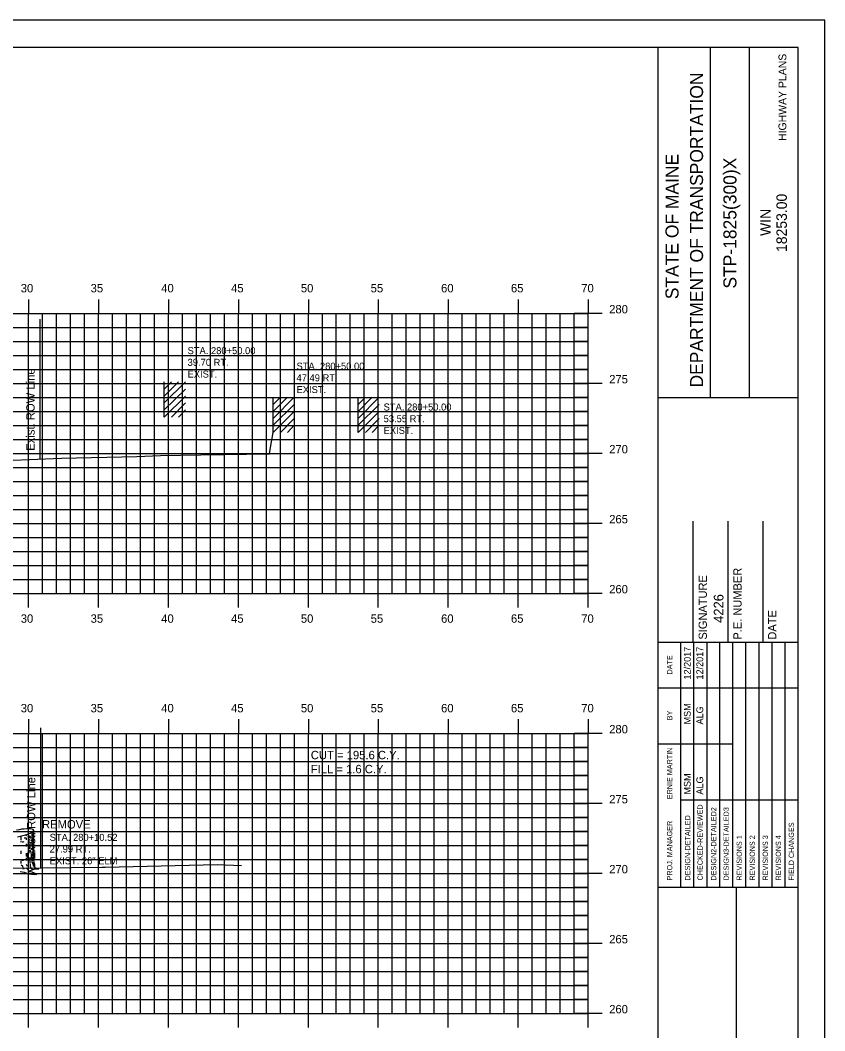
# Model space of a CAD drawing. Extents: x 855121 to 855291, y 366268 to 366378.
# Drawn here: x 855233.9 to 855291.3, y 366306 to 366378.2 of the extents above; entities that cross this region are included whole.
import ezdxf

# ---------------------------------------------------------------- set-up
doc = ezdxf.new("R2010")
doc.units = 0
for name, color, linetype in [('ANNOTATION', 7, 'Continuous'), ('BORDER', 7, 'Continuous'), ('D_Text_Monospaced', 7, 'Continuous'), ('E_ROW_Line', 7, 'Continuous'), ('H_V ANNOTATION', 7, 'Continuous'), ('HIGHWAY_TITLE', 7, 'Continuous'), ('MAJOR', 7, 'Continuous'), ('MINOR', 7, 'Continuous'), ('PLOT BOUNDARY', 7, 'Continuous'), ('S_Buildings', 7, 'Continuous'), ('S_Buildings_Attachments', 7, 'Continuous'), ('S_Roadway_Centerline', 7, 'Continuous'), ('S_Trees_Decid_Pay', 7, 'Continuous')]:
    doc.layers.add(name, color=color, linetype=linetype)

msp = doc.modelspace()

# ---------------------------------------------------------------- linework, layer by layer
at = {"layer": 'BORDER'}
for p, q in [((855289.442, 366376.236), (855129.442, 366376.236)), ((855279.442, 366271.236), (855279.442, 366376.239)), ((855283.171, 366351.234), (855283.171, 366376.234)), ((855285.966, 366351.234), (855285.966, 366376.234)), ((855289.442, 366271.236), (855289.442, 366376.236)), ((855279.443, 366351.231), (855289.442, 366351.231)), ((855281.942, 366333.739), (855281.942, 366342.387)), ((855284.442, 366333.739), (855284.442, 366342.387)), ((855286.942, 366333.739), (855286.942, 366342.387)), ((855279.442, 366333.739), (855289.442, 366333.739)), ((855279.442, 366316.239), (855289.442, 366316.239)), ((855285.033, 366281.239), (855285.033, 366316.239))]:
    msp.add_line(p, q, dxfattribs=at)
for points in [[(855281.057, 366330.489), (855281.057, 366333.739)], [(855281.99, 366316.242), (855281.99, 366333.739)], [(855282.921, 366333.739), (855282.921, 366316.242)], [(855283.853, 366316.242), (855283.853, 366333.739)], [(855284.785, 366316.242), (855284.785, 366333.739)], [(855285.716, 366316.242), (855285.716, 366333.739)], [(855286.648, 366316.242), (855286.648, 366333.739)], [(855287.58, 366316.242), (855287.58, 366333.739)], [(855288.511, 366316.242), (855288.511, 366333.739)], [(855281.058, 366316.242), (855281.058, 366333.033)], [(855279.442, 366330.489), (855289.442, 366330.489)], [(855279.442, 366326.489), (855281.058, 366326.489)], [(855281.057, 366326.489), (855284.784, 366326.489)], [(855281.057, 366322.489), (855289.442, 366322.489)]]:
    msp.add_lwpolyline(points, dxfattribs=at)
at = {"layer": 'E_ROW_Line'}
for p, q in [((855235.284, 366346.822), (855235.284, 366356.822)), ((855235.331, 366317.628), (855235.331, 366327.628))]:
    msp.add_line(p, q, dxfattribs=at)
at = {"layer": 'MAJOR'}
for p, q in [((855234.442, 366358.238), (855234.442, 366357.236)), ((855239.442, 366358.238), (855239.442, 366357.236)), ((855244.442, 366358.238), (855244.442, 366357.236)), ((855249.442, 366358.238), (855249.442, 366357.236)), ((855254.442, 366358.238), (855254.442, 366357.236)), ((855259.442, 366358.238), (855259.442, 366357.236)), ((855264.442, 366358.238), (855264.442, 366357.236)), ((855269.442, 366358.238), (855269.442, 366357.236)), ((855274.442, 366358.238), (855274.442, 366357.236)), ((855134.442, 366357.236), (855274.442, 366357.236)), ((855134.442, 366357.236), (855274.442, 366357.236)), ((855234.442, 366337.236), (855234.442, 366357.236)), ((855239.442, 366337.236), (855239.442, 366357.236)), ((855244.442, 366337.236), (855244.442, 366357.236)), ((855249.442, 366337.236), (855249.442, 366357.236)), ((855254.442, 366337.236), (855254.442, 366357.236)), ((855259.442, 366337.236), (855259.442, 366357.236)), ((855264.442, 366337.236), (855264.442, 366357.236)), ((855269.442, 366337.236), (855269.442, 366357.236)), ((855275.444, 366357.236), (855273.44, 366357.236)), ((855274.442, 366337.236), (855274.442, 366357.236)), ((855274.442, 366337.236), (855274.442, 366357.236)), ((855134.442, 366352.236), (855274.442, 366352.236)), ((855275.444, 366352.236), (855273.44, 366352.236)), ((855134.442, 366347.236), (855274.442, 366347.236)), ((855275.444, 366347.236), (855273.44, 366347.236)), ((855134.442, 366342.236), (855274.442, 366342.236)), ((855275.444, 366342.236), (855273.44, 366342.236)), ((855134.442, 366337.236), (855274.442, 366337.236)), ((855134.442, 366337.236), (855274.442, 366337.236)), ((855234.442, 366336.234), (855234.442, 366337.236)), ((855239.442, 366336.234), (855239.442, 366337.236)), ((855244.442, 366336.234), (855244.442, 366337.236)), ((855249.442, 366336.234), (855249.442, 366337.236)), ((855254.442, 366336.234), (855254.442, 366337.236)), ((855259.442, 366336.234), (855259.442, 366337.236)), ((855264.442, 366336.234), (855264.442, 366337.236)), ((855269.442, 366336.234), (855269.442, 366337.236)), ((855275.444, 366337.236), (855273.44, 366337.236)), ((855274.442, 366336.234), (855274.442, 366337.236)), ((855234.442, 366328.238), (855234.442, 366327.236)), ((855239.442, 366328.238), (855239.442, 366327.236)), ((855244.442, 366328.238), (855244.442, 366327.236)), ((855249.442, 366328.238), (855249.442, 366327.236)), ((855254.442, 366328.238), (855254.442, 366327.236)), ((855259.442, 366328.238), (855259.442, 366327.236)), ((855264.442, 366328.238), (855264.442, 366327.236)), ((855269.442, 366328.238), (855269.442, 366327.236)), ((855274.442, 366328.238), (855274.442, 366327.236)), ((855134.442, 366327.236), (855274.442, 366327.236)), ((855134.442, 366327.236), (855274.442, 366327.236)), ((855234.442, 366307.236), (855234.442, 366327.236)), ((855239.442, 366307.236), (855239.442, 366327.236)), ((855244.442, 366307.236), (855244.442, 366327.236)), ((855249.442, 366307.236), (855249.442, 366327.236)), ((855254.442, 366307.236), (855254.442, 366327.236)), ((855259.442, 366307.236), (855259.442, 366327.236)), ((855264.442, 366307.236), (855264.442, 366327.236)), ((855269.442, 366307.236), (855269.442, 366327.236)), ((855275.444, 366327.236), (855273.44, 366327.236)), ((855274.442, 366307.236), (855274.442, 366327.236)), ((855274.442, 366307.236), (855274.442, 366327.236)), ((855134.442, 366322.236), (855274.442, 366322.236)), ((855275.444, 366322.236), (855273.44, 366322.236)), ((855134.442, 366317.236), (855274.442, 366317.236)), ((855275.444, 366317.236), (855273.44, 366317.236)), ((855134.442, 366312.236), (855274.442, 366312.236)), ((855275.444, 366312.236), (855273.44, 366312.236)), ((855134.442, 366307.236), (855274.442, 366307.236)), ((855134.442, 366307.236), (855274.442, 366307.236)), ((855234.442, 366306.234), (855234.442, 366307.236)), ((855239.442, 366306.234), (855239.442, 366307.236)), ((855244.442, 366306.234), (855244.442, 366307.236)), ((855249.442, 366306.234), (855249.442, 366307.236)), ((855254.442, 366306.234), (855254.442, 366307.236)), ((855259.442, 366306.234), (855259.442, 366307.236)), ((855264.442, 366306.234), (855264.442, 366307.236)), ((855269.442, 366306.234), (855269.442, 366307.236)), ((855275.444, 366307.236), (855273.44, 366307.236)), ((855274.442, 366306.234), (855274.442, 366307.236))]:
    msp.add_line(p, q, dxfattribs=at)
at = {"layer": 'MINOR'}
for p, q in [((855235.442, 366337.236), (855235.442, 366357.236)), ((855236.442, 366337.236), (855236.442, 366357.236)), ((855237.442, 366337.236), (855237.442, 366357.236)), ((855238.442, 366337.236), (855238.442, 366357.236)), ((855240.442, 366337.236), (855240.442, 366357.236)), ((855241.442, 366337.236), (855241.442, 366357.236)), ((855242.442, 366337.236), (855242.442, 366357.236)), ((855243.442, 366337.236), (855243.442, 366357.236)), ((855245.442, 366337.236), (855245.442, 366357.236)), ((855246.442, 366337.236), (855246.442, 366357.236)), ((855247.442, 366337.236), (855247.442, 366357.236)), ((855248.442, 366337.236), (855248.442, 366357.236)), ((855250.442, 366337.236), (855250.442, 366357.236)), ((855251.442, 366337.236), (855251.442, 366357.236)), ((855252.442, 366337.236), (855252.442, 366357.236)), ((855253.442, 366337.236), (855253.442, 366357.236)), ((855255.442, 366337.236), (855255.442, 366357.236)), ((855256.442, 366337.236), (855256.442, 366357.236)), ((855257.442, 366337.236), (855257.442, 366357.236)), ((855258.442, 366337.236), (855258.442, 366357.236)), ((855260.442, 366337.236), (855260.442, 366357.236)), ((855261.442, 366337.236), (855261.442, 366357.236)), ((855262.442, 366337.236), (855262.442, 366357.236)), ((855263.442, 366337.236), (855263.442, 366357.236)), ((855265.442, 366337.236), (855265.442, 366357.236)), ((855266.442, 366337.236), (855266.442, 366357.236)), ((855267.442, 366337.236), (855267.442, 366357.236)), ((855268.442, 366337.236), (855268.442, 366357.236)), ((855270.442, 366337.236), (855270.442, 366357.236)), ((855271.442, 366337.236), (855271.442, 366357.236)), ((855272.442, 366337.236), (855272.442, 366357.236)), ((855273.442, 366337.236), (855273.442, 366357.236)), ((855134.442, 366356.236), (855274.442, 366356.236)), ((855274.442, 366356.236), (855273.44, 366356.236)), ((855134.442, 366355.236), (855274.442, 366355.236)), ((855274.442, 366355.236), (855273.44, 366355.236)), ((855134.442, 366354.236), (855274.442, 366354.236)), ((855274.442, 366354.236), (855273.44, 366354.236)), ((855134.442, 366353.236), (855274.442, 366353.236)), ((855274.442, 366353.236), (855273.44, 366353.236)), ((855134.442, 366351.236), (855274.442, 366351.236)), ((855274.442, 366351.236), (855273.44, 366351.236)), ((855134.442, 366350.236), (855274.442, 366350.236)), ((855274.442, 366350.236), (855273.44, 366350.236)), ((855134.442, 366349.236), (855274.442, 366349.236)), ((855274.442, 366349.236), (855273.44, 366349.236)), ((855134.442, 366348.236), (855274.442, 366348.236)), ((855274.442, 366348.236), (855273.44, 366348.236)), ((855134.442, 366346.236), (855274.442, 366346.236)), ((855274.442, 366346.236), (855273.44, 366346.236)), ((855134.442, 366345.236), (855274.442, 366345.236)), ((855274.442, 366345.236), (855273.44, 366345.236)), ((855134.442, 366344.236), (855274.442, 366344.236)), ((855274.442, 366344.236), (855273.44, 366344.236)), ((855134.442, 366343.236), (855274.442, 366343.236)), ((855274.442, 366343.236), (855273.44, 366343.236)), ((855134.442, 366341.236), (855274.442, 366341.236)), ((855274.442, 366341.236), (855273.44, 366341.236)), ((855134.442, 366340.236), (855274.442, 366340.236)), ((855274.442, 366340.236), (855273.44, 366340.236)), ((855134.442, 366339.236), (855274.442, 366339.236)), ((855274.442, 366339.236), (855273.44, 366339.236)), ((855134.442, 366338.236), (855274.442, 366338.236)), ((855274.442, 366338.236), (855273.44, 366338.236)), ((855235.442, 366307.236), (855235.442, 366327.236)), ((855236.442, 366307.236), (855236.442, 366327.236)), ((855237.442, 366307.236), (855237.442, 366327.236)), ((855238.442, 366307.236), (855238.442, 366327.236)), ((855240.442, 366307.236), (855240.442, 366327.236)), ((855241.442, 366307.236), (855241.442, 366327.236)), ((855242.442, 366307.236), (855242.442, 366327.236)), ((855243.442, 366307.236), (855243.442, 366327.236)), ((855245.442, 366307.236), (855245.442, 366327.236)), ((855246.442, 366307.236), (855246.442, 366327.236)), ((855247.442, 366307.236), (855247.442, 366327.236)), ((855248.442, 366307.236), (855248.442, 366327.236)), ((855250.442, 366307.236), (855250.442, 366327.236)), ((855251.442, 366307.236), (855251.442, 366327.236)), ((855252.442, 366307.236), (855252.442, 366327.236)), ((855253.442, 366307.236), (855253.442, 366327.236)), ((855255.442, 366307.236), (855255.442, 366327.236)), ((855256.442, 366307.236), (855256.442, 366327.236)), ((855257.442, 366307.236), (855257.442, 366327.236)), ((855258.442, 366307.236), (855258.442, 366327.236)), ((855260.442, 366307.236), (855260.442, 366327.236)), ((855261.442, 366307.236), (855261.442, 366327.236)), ((855262.442, 366307.236), (855262.442, 366327.236)), ((855263.442, 366307.236), (855263.442, 366327.236)), ((855265.442, 366307.236), (855265.442, 366327.236)), ((855266.442, 366307.236), (855266.442, 366327.236)), ((855267.442, 366307.236), (855267.442, 366327.236)), ((855268.442, 366307.236), (855268.442, 366327.236)), ((855270.442, 366307.236), (855270.442, 366327.236)), ((855271.442, 366307.236), (855271.442, 366327.236)), ((855272.442, 366307.236), (855272.442, 366327.236)), ((855273.442, 366307.236), (855273.442, 366327.236)), ((855134.442, 366326.236), (855274.442, 366326.236)), ((855274.442, 366326.236), (855273.44, 366326.236)), ((855134.442, 366325.236), (855274.442, 366325.236)), ((855274.442, 366325.236), (855273.44, 366325.236)), ((855134.442, 366324.236), (855274.442, 366324.236)), ((855274.442, 366324.236), (855273.44, 366324.236)), ((855134.442, 366323.236), (855274.442, 366323.236)), ((855274.442, 366323.236), (855273.44, 366323.236)), ((855134.442, 366321.236), (855274.442, 366321.236)), ((855274.442, 366321.236), (855273.44, 366321.236)), ((855134.442, 366320.236), (855274.442, 366320.236)), ((855274.442, 366320.236), (855273.44, 366320.236)), ((855134.442, 366319.236), (855274.442, 366319.236)), ((855274.442, 366319.236), (855273.44, 366319.236)), ((855134.442, 366318.236), (855274.442, 366318.236)), ((855274.442, 366318.236), (855273.44, 366318.236)), ((855134.442, 366316.236), (855274.442, 366316.236)), ((855274.442, 366316.236), (855273.44, 366316.236)), ((855134.442, 366315.236), (855274.442, 366315.236)), ((855274.442, 366315.236), (855273.44, 366315.236)), ((855134.442, 366314.236), (855274.442, 366314.236)), ((855274.442, 366314.236), (855273.44, 366314.236)), ((855134.442, 366313.236), (855274.442, 366313.236)), ((855274.442, 366313.236), (855273.44, 366313.236)), ((855134.442, 366311.236), (855274.442, 366311.236)), ((855274.442, 366311.236), (855273.44, 366311.236)), ((855134.442, 366310.236), (855274.442, 366310.236)), ((855274.442, 366310.236), (855273.44, 366310.236)), ((855134.442, 366309.236), (855274.442, 366309.236)), ((855274.442, 366309.236), (855273.44, 366309.236)), ((855134.442, 366308.236), (855274.442, 366308.236)), ((855274.442, 366308.236), (855273.44, 366308.236))]:
    msp.add_line(p, q, dxfattribs=at)
at = {"layer": 'PLOT BOUNDARY'}
msp.add_lwpolyline([(855121.349, 366268.177), (855291.349, 366268.177), (855291.349, 366378.177), (855121.349, 366378.177)], close=True, dxfattribs=at)
at = {"layer": 'S_Buildings'}
for p, q in [((855251.931, 366348.718), (855251.931, 366351.245)), ((855251.931, 366349.735), (855253.44, 366351.245)), ((855251.931, 366350.228), (855252.948, 366351.245)), ((855251.931, 366350.72), (855252.456, 366351.245)), ((855257.991, 366348.718), (855257.991, 366351.245)), ((855257.991, 366349.736), (855259.5, 366351.245)), ((855257.991, 366350.228), (855259.008, 366351.245)), ((855257.991, 366350.72), (855258.516, 366351.245)), ((855251.931, 366349.243), (855253.44, 366350.72)), ((855257.991, 366349.243), (855259.5, 366350.72)), ((855251.931, 366348.718), (855253.44, 366350.228)), ((855252.456, 366348.718), (855253.44, 366349.735)), ((855257.991, 366348.718), (855259.5, 366350.228)), ((855258.516, 366348.718), (855259.5, 366349.736)), ((855252.948, 366348.718), (855253.44, 366349.243)), ((855259.008, 366348.718), (855259.5, 366349.243))]:
    msp.add_line(p, q, dxfattribs=at)
at = {"layer": 'S_Buildings_Attachments'}
for p, q in [((855244.146, 366349.825), (855244.146, 366352.351)), ((855244.146, 366350.842), (855245.655, 366352.351)), ((855244.146, 366351.334), (855245.163, 366352.351)), ((855244.146, 366351.826), (855244.671, 366352.351)), ((855244.146, 366350.35), (855245.655, 366351.826)), ((855244.146, 366349.825), (855245.655, 366351.334)), ((855244.671, 366349.825), (855245.655, 366350.842)), ((855245.163, 366349.825), (855245.655, 366350.35))]:
    msp.add_line(p, q, dxfattribs=at)
at = {"layer": 'S_Roadway_Centerline'}
for points in [[(855225.306, 366346.406), (855236.796, 366346.885), (855242.187, 366347.024), (855243.875, 366347.078), (855246.754, 366347.142), (855251.665, 366347.196), (855251.741, 366347.66), (855251.931, 366348.719)], [(855228.791, 366317.564), (855239.683, 366317.672), (855239.926, 366317.671), (855247.916, 366317.86), (855249.671, 366317.803)]]:
    msp.add_lwpolyline(points, dxfattribs=at)
at = {"layer": 'S_Trees_Decid_Pay'}
for p, q in [((855234.277, 366320.003), (855234.277, 366319.917)), ((855234.681, 366320.17), (855234.681, 366319.917)), ((855234.762, 366320.215), (855234.762, 366320.094)), ((855234.762, 366320.042), (855234.762, 366319.828)), ((855233.893, 366319.902), (855233.893, 366319.622)), ((855233.893, 366319.557), (855233.893, 366319.454)), ((855234.277, 366319.776), (855234.277, 366319.637)), ((855234.277, 366319.351), (855234.277, 366319.159)), ((855234.549, 366319.917), (855234.549, 366319.725)), ((855234.549, 366319.474), (855234.549, 366319.196)), ((855234.681, 366319.82), (855234.681, 366319.557)), ((855234.681, 366319.459), (855234.681, 366319.151)), ((855234.762, 366319.783), (855234.762, 366319.445)), ((855234.762, 366319.328), (855234.762, 366318.967)), ((855233.893, 366318.842), (855233.893, 366318.622)), ((855234.277, 366318.679), (855234.277, 366318.471)), ((855234.549, 366319.151), (855234.549, 366319.042)), ((855234.549, 366318.908), (855234.549, 366318.679)), ((855234.681, 366319.062), (855234.681, 366318.996)), ((855234.681, 366318.762), (855234.681, 366318.665)), ((855234.681, 366318.614), (855234.681, 366318.253)), ((855234.762, 366318.931), (855234.762, 366318.482)), ((855233.893, 366318.122), (855233.893, 366317.948)), ((855234.272, 366317.893), (855234.352, 366317.761)), ((855234.277, 366318.35), (855234.277, 366318.15)), ((855234.549, 366318.35), (855234.549, 366317.967)), ((855234.681, 366318.202), (855234.681, 366318.035)), ((855234.762, 366318.416), (855234.762, 366318.134))]:
    msp.add_line(p, q, dxfattribs=at)
for points in [[(855233.844, 366317.366), (855234.13, 366317.31), (855234.428, 366317.203), (855234.887, 366317.154), (855235.042, 366317.166), (855234.7, 366317.316), (855234.496, 366317.347), (855234.508, 366317.421), (855234.768, 366317.52), (855234.943, 366317.551), (855235.184, 366317.563), (855234.986, 366317.601), (855234.924, 366317.637), (855234.9, 366317.724), (855234.887, 366317.893), (855234.842, 366317.979), (855234.814, 366318.22), (855234.814, 366320.306)], [(855234.39, 366318.485), (855234.389, 366318.562), (855234.381, 366318.628)], [(855233.911, 366317.833), (855234.014, 366317.782), (855234.029, 366317.576), (855234.132, 366317.547)], [(855234.566, 366317.907), (855234.566, 366317.702), (855234.624, 366317.592), (855234.721, 366317.576)], [(855234.706, 366317.981), (855234.778, 366317.878), (855234.778, 366317.753)], [(855234.763, 366318.062), (855234.824, 366317.901), (855234.838, 366317.776), (855234.83, 366317.679)], [(855234.496, 366317.347), (855234.41, 366317.489), (855234.278, 366317.631)]]:
    msp.add_lwpolyline(points, dxfattribs=at)
for centre, radius, start, end in [((855234.727, 366314.304), 6.126, 93.69441, 100.77788), ((855232.524, 366325.873), 6.126, 280.77788, 287.86134), ((855234.416, 366319.121), 1.299, 78.27788, 93.69441), ((855234.005, 366321.279), 1.299, 287.86134, 303.27788), ((855234.582, 366319.924), 0.48, 69.98432, 78.27788), ((855234.455, 366320.594), 0.48, 303.27788, 311.57144), ((855234.69, 366320.22), 0.164, 55.77788, 69.98432), ((855234.664, 366320.358), 0.164, 311.57144, 325.77788), ((855234.722, 366320.267), 0.107, 45.9547, 55.77788), ((855234.715, 366320.008), 0.109, 315, 324.82628), ((855234.752, 366320.298), 0.0645, 33.27788, 45.9547), ((855234.711, 366320.326), 0.107, 325.77788, 335.60106), ((855234.75, 366319.983), 0.0657, 324.82628, 337.5), ((855234.76, 366320.303), 0.0544, 22.46002, 33.27788), ((855234.75, 366320.308), 0.0645, 335.60106, 348.27788), ((855234.767, 366320.306), 0.0467, 10.77788, 22.46002), ((855234.76, 366319.979), 0.0554, 337.5, 348.31854), ((855234.767, 366320.306), 0.0467, 359.09574, 10.77788), ((855234.76, 366320.306), 0.0544, 348.27788, 359.09574), ((855233.626, 366325.395), 5.916, 273.53821, 274.89239), ((855233.627, 366325.656), 5.916, 274.95145, 276.30875), ((855233.626, 366325.132), 5.916, 276.31835, 277.15463), ((855234.201, 366320.544), 1.292, 277.15463, 278.36619), ((855234.202, 366321.068), 1.292, 285.56513, 289.09156), ((855234.201, 366320.807), 1.292, 288.08294, 292.5), ((855234.201, 366320.544), 1.292, 291.8071, 292.5), ((855234.511, 366319.798), 0.484, 292.5, 300.80756), ((855234.511, 366320.061), 0.484, 297.41617, 300.80756), ((855234.673, 366319.788), 0.166, 300.80756, 315), ((855234.673, 366319.525), 0.166, 300.80756, 301.6001), ((855234.674, 366320.049), 0.166, 301.67004, 315), ((855234.714, 366319.748), 0.109, 315, 324.82628), ((855234.749, 366319.723), 0.0657, 324.82628, 337.5), ((855234.759, 366319.719), 0.0554, 337.5, 348.31854), ((855234.201, 366320.286), 1.292, 279.25654, 285.6105), ((855234.201, 366320.029), 1.292, 285.61049, 290.10015), ((855234.511, 366319.017), 0.484, 292.5, 300.80756), ((855234.511, 366319.54), 0.484, 294.63721, 300.80756), ((855234.673, 366319.267), 0.166, 300.80756, 315), ((855234.673, 366318.744), 0.166, 300.80756, 302.06939), ((855234.673, 366319.01), 0.166, 302.06939, 315), ((855234.714, 366319.227), 0.109, 315, 324.82628), ((855234.714, 366318.969), 0.109, 315, 324.82628), ((855234.749, 366319.202), 0.0657, 324.82628, 337.5), ((855234.749, 366318.944), 0.0657, 324.82628, 337.5), ((855234.759, 366319.198), 0.0554, 337.5, 348.31854), ((855234.759, 366318.94), 0.0554, 337.5, 348.31854), ((855234.759, 366318.675), 0.0554, 337.5, 348.31854), ((855233.626, 366324.08), 5.916, 273.26366, 274.46102), ((855233.626, 366324.351), 5.916, 276.31835, 277.15463), ((855233.626, 366324.08), 5.916, 276.31835, 277.15463), ((855234.201, 366319.764), 1.292, 277.15463, 278.37952), ((855234.201, 366319.492), 1.292, 277.15463, 278.36619), ((855234.201, 366319.492), 1.292, 285.61049, 289.15336), ((855234.211, 366319.238), 1.292, 291.36963, 292.0604), ((855234.511, 366318.488), 0.484, 292.5, 296.54992), ((855234.673, 366318.472), 0.166, 302.06939, 315), ((855234.714, 366318.432), 0.109, 315, 324.82628), ((855234.749, 366318.407), 0.0657, 324.82628, 337.5), ((855234.759, 366318.403), 0.0554, 337.5, 348.31854)]:
    msp.add_arc(centre, radius, start, end, dxfattribs=at)

# ---------------------------------------------------------------- texts
at = {"layer": 'ANNOTATION'}
msp.add_text('4226', height=0.69, rotation=90, dxfattribs=at).set_placement((855284.107, 366335.13))
for s, p in [('CUT = 195.6 C.Y.', (855254.618, 366325.386)), ('FILL = 1.6 C.Y.', (855254.618, 366324.384)), ('REMOVE', (855235.41, 366320.44))]:
    msp.add_text(s, height=0.6, dxfattribs=at).set_placement(p)
at = {"layer": 'BORDER'}
for s, height, p in [('DEPARTMENT OF TRANSPORTATION', 0.93176, (855282.649, 366351.942)), ('STATE OF MAINE', 0.93176, (855280.897, 366358.248)), ('STP-1825(300)X', 0.93176, (855285.034, 366359.008)), ('18253.00', 0.7453, (855288.638, 366361.623)), ('WIN', 0.7453, (855287.479, 366362.766)), ('P.E. NUMBER', 0.59055, (855285.403, 366333.932)), ('SIGNATURE', 0.5906, (855282.923, 366333.932)), ('DATE', 0.5906, (855287.883, 366333.932)), ('12/2017', 0.4845, (855281.765, 366331.081)), ('12/2017', 0.4845, (855282.659, 366331.081)), ('DATE', 0.3714, (855280.446, 366331.445)), ('MSM', 0.4845, (855281.765, 366327.872)), ('BY', 0.3714, (855280.446, 366328.174)), ('ALG', 0.4845, (855282.659, 366327.872)), ('ERNIE MARTIN', 0.37275, (855280.446, 366322.531)), ('MSM', 0.4845, (855281.765, 366322.863)), ('ALG', 0.4845, (855282.659, 366322.863)), ('CHECKED-REVIEWED', 0.37275, (855282.623, 366316.727)), ('DESIGN2-DETAILED2', 0.37275, (855283.592, 366316.727)), ('DESIGN3-DETAILED3', 0.37275, (855284.486, 366316.727)), ('PROJ. MANAGER', 0.37275, (855280.446, 366316.727)), ('DESIGN-DETAILED', 0.37275, (855281.729, 366316.727)), ('FIELD CHANGES', 0.37275, (855289.145, 366316.727)), ('REVISIONS 1', 0.37275, (855285.418, 366316.727)), ('REVISIONS 2', 0.37275, (855286.35, 366316.727)), ('REVISIONS 3', 0.37275, (855287.281, 366316.727)), ('REVISIONS 4', 0.37275, (855288.213, 366316.727))]:
    msp.add_text(s, height=height, rotation=90, dxfattribs=at).set_placement(p)
at = {"layer": 'D_Text_Monospaced'}
for s, height, p in [('STA. 280+50.00', 0.49998, (855245.812, 366354.323)), ('39.70 RT.', 0.5, (855245.812, 366353.489)), ('EXIST. ', 0.5, (855245.812, 366352.649)), ('STA. 280+50.00', 0.49998, (855253.598, 366353.217)), ('47.49 RT.', 0.5, (855253.598, 366352.383)), ('EXIST. ', 0.5, (855253.598, 366351.543)), ('STA. 280+50.00', 0.49998, (855259.82, 366350.297)), ('53.55 RT.', 0.5, (855259.82, 366349.463)), ('EXIST. ', 0.5, (855259.82, 366348.623)), ('STA. 280+10.52', 0.49998, (855235.955, 366319.558)), ('27.99 RT.', 0.5, (855235.955, 366318.724)), ('EXIST. 26" ELM', 0.49998, (855235.955, 366317.884))]:
    msp.add_text(s, height=height, dxfattribs=at).set_placement(p)
at = {"layer": 'E_ROW_Line'}
for p in [(855234.884, 366347.422), (855234.931, 366318.228)]:
    msp.add_text('Exist. ROW Line', height=0.6, rotation=90, dxfattribs=at).set_placement(p)
at = {"layer": 'H_V ANNOTATION'}
for s, p in [('30', (855233.891, 366358.736)), ('35', (855238.883, 366358.736)), ('40', (855243.928, 366358.736)), ('45', (855248.92, 366358.736)), ('50', (855253.907, 366358.736)), ('55', (855258.899, 366358.736)), ('60', (855263.928, 366358.736)), ('65', (855268.92, 366358.736)), ('70', (855273.944, 366358.736)), ('280', (855275.942, 366357.236)), ('275', (855275.942, 366352.236)), ('270', (855275.942, 366347.236)), ('265', (855275.942, 366342.236)), ('260', (855275.942, 366337.236)), ('30', (855233.891, 366335.136)), ('35', (855238.883, 366335.136)), ('40', (855243.928, 366335.136)), ('45', (855248.92, 366335.136)), ('50', (855253.907, 366335.136)), ('55', (855258.899, 366335.136)), ('60', (855263.928, 366335.136)), ('65', (855268.92, 366335.136)), ('70', (855273.944, 366335.136)), ('30', (855233.891, 366328.736)), ('35', (855238.883, 366328.736)), ('40', (855243.928, 366328.736)), ('45', (855248.92, 366328.736)), ('50', (855253.907, 366328.736)), ('55', (855258.899, 366328.736)), ('60', (855263.928, 366328.736)), ('65', (855268.92, 366328.736)), ('70', (855273.944, 366328.736)), ('280', (855275.942, 366327.236)), ('275', (855275.942, 366322.236)), ('270', (855275.942, 366317.236)), ('265', (855275.942, 366312.236)), ('260', (855275.942, 366307.236))]:
    msp.add_text(s, height=0.6, dxfattribs=at).set_placement(p)
at = {"layer": 'HIGHWAY_TITLE'}
msp.add_text('HIGHWAY PLANS', height=0.55901, rotation=90, dxfattribs=at).set_placement((855288.6, 366369.552))

doc.saveas('drawing.dxf')
